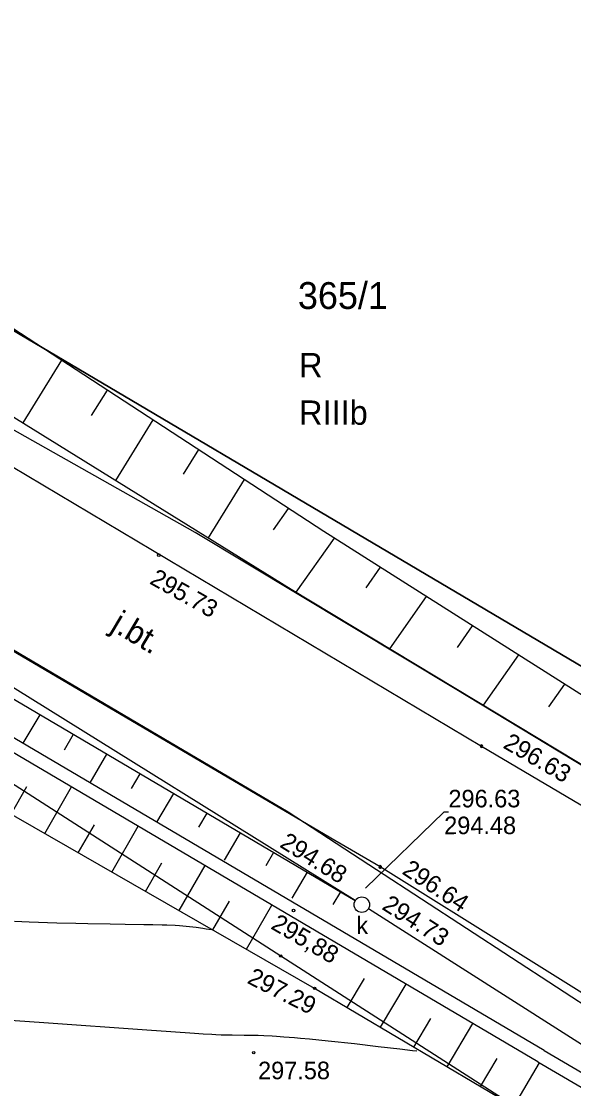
# Model space of a CAD drawing. Extents: x 7477803 to 7478145, y 5500698 to 5500984.
# Drawn here: x 7477973.66 to 7477995.02, y 5500861.83 to 5500903.15 of the extents above; entities that cross this region are included whole.
import ezdxf

# ---------------------------------------------------------------- set-up
doc = ezdxf.new("R2010")
doc.units = 0
for name, color, linetype in [('203-Punkt załamania granicy działki nie stabilizowany', 7, 'Continuous'), ('eNN', 7, 'Continuous'), ('gr_dzialki', 7, 'Continuous'), ('gr_klasy', 7, 'Continuous'), ('jezdnia', 7, 'Continuous'), ('k', 7, 'Continuous'), ('k_elem_naziemne', 7, 'Continuous'), ('k_rzedne', 7, 'Continuous'), ('nr_dzialki', 7, 'Continuous'), ('opis_klasy', 7, 'Continuous'), ('opis_uzytek', 7, 'Continuous'), ('opisy_drog', 7, 'Continuous'), ('pkt_wys', 7, 'Continuous'), ('rowy', 7, 'Continuous'), ('skarp_wypel', 7, 'Continuous'), ('skarpa_gora', 7, 'Continuous'), ('w', 7, 'Continuous'), ('warst_ciagla', 7, 'Continuous'), ('warst_przeryw', 7, 'Continuous')]:
    doc.layers.add(name, color=color, linetype=linetype)

# ---------------------------------------------------------------- blocks, each defined once
blk = doc.blocks.new('203')
blk.add_circle((0, 0), 0.045)
blk = doc.blocks.new('506_5_1')
at = {"layer": 'k_elem_naziemne'}
blk.add_circle((0, 0), 0.3, dxfattribs=at)
blk = doc.blocks.new('801_3')
at = {"layer": 'pkt_wys'}
blk.add_circle((0, 0), 0.045, dxfattribs=at)
blk.add_circle((0, 0), 0.045, dxfattribs=at)
blk = doc.blocks.new('801_5')
at = {"layer": 'pkt_wys'}
blk.add_circle((0, 0), 0.05, dxfattribs=at)
blk.add_circle((0, 0), 0.05, dxfattribs=at)
blk = doc.blocks.new('801_5_4')
at = {"layer": 'pkt_wys'}
blk.add_circle((0, 0), 0.05, dxfattribs=at)
blk.add_circle((0, 0), 0.05, dxfattribs=at)

msp = doc.modelspace()

# ---------------------------------------------------------------- linework, layer by layer
at = {"layer": 'eNN'}
msp.add_lwpolyline([(7478044.292, 5500829.332), (7478043.979, 5500830.08), (7478036.967, 5500842.126), (7478033.374, 5500847.92), (7478030.266, 5500851.792), (7478027.179, 5500855.154), (7478025.031, 5500856.9), (7478008.369, 5500866.572), (7477997.07, 5500873.297), (7477990.438, 5500877.31), (7477980.374, 5500883.358), (7477966.627, 5500891.122), (7477956.111, 5500897.36), (7477948.099, 5500902.324), (7477944.454, 5500904.573)], dxfattribs=at)
at = {"layer": 'gr_dzialki'}
for points in [[(7477995.4, 5500878.14), (7477967.16, 5500894.83)], [(7477983.69, 5500866.96), (7477970.37, 5500875.52)], [(7478015.58, 5500846.47), (7477983.69, 5500866.96)]]:
    msp.add_lwpolyline(points, dxfattribs=at)
at = {"layer": 'gr_klasy'}
for points in [[(7477967.16, 5500894.83), (7477995.4, 5500878.14)], [(7477983.69, 5500866.96), (7477970.37, 5500875.52)], [(7478015.58, 5500846.47), (7477983.69, 5500866.96)]]:
    msp.add_lwpolyline(points, dxfattribs=at)
at = {"layer": 'jezdnia'}
for points in [[(7477987.535, 5500870.412), (7477985.624, 5500871.53), (7477967.072, 5500882.45), (7477949.37, 5500893.011), (7477933.46, 5500902.673), (7477915.126, 5500915.133), (7477901.636, 5500924.498), (7477893.479, 5500930.51)], [(7477953.13, 5500897.937), (7477970.226, 5500887.733), (7477991.46, 5500875.087)], [(7477991.46, 5500875.087), (7478007.83, 5500865.404), (7478012.783, 5500862.5)], [(7478010.61, 5500855.711), (7478003.516, 5500860.43), (7477987.535, 5500870.412)]]:
    msp.add_lwpolyline(points, dxfattribs=at)
at = {"layer": 'k'}
msp.add_line((7477986.572, 5500869.11), (7477945.873, 5500894.448), dxfattribs=at)
msp.add_lwpolyline([(7477999.978, 5500860.567), (7477987.079, 5500868.79)], dxfattribs=at)
at = {"layer": 'k_rzedne'}
msp.add_lwpolyline([(7477990.178, 5500872.537), (7477989.998, 5500872.537), (7477986.973, 5500869.585)], dxfattribs=at)
at = {"layer": 'pkt_wys'}
for points in [[(7477991.428, 5500875.048), (7477991.46, 5500875.087), (7477991.434, 5500875.13)], [(7477991.434, 5500875.13), (7477991.46, 5500875.087), (7477991.428, 5500875.048)], [(7477991.428, 5500875.048), (7477991.46, 5500875.087), (7477991.434, 5500875.13)], [(7477991.434, 5500875.13), (7477991.46, 5500875.087), (7477991.428, 5500875.048)], [(7477987.495, 5500870.382), (7477987.535, 5500870.412), (7477987.567, 5500870.451)], [(7477987.567, 5500870.451), (7477987.535, 5500870.412), (7477987.495, 5500870.382)], [(7477987.495, 5500870.382), (7477987.535, 5500870.412), (7477987.567, 5500870.451)], [(7477987.567, 5500870.451), (7477987.535, 5500870.412), (7477987.495, 5500870.382)]]:
    msp.add_lwpolyline(points, dxfattribs=at)
for centre, start, end in [((7477991.46, 5500875.087), 120.6707, 229.9806), ((7477991.46, 5500875.087), 120.6707, 229.9806), ((7477991.46, 5500875.087), 229.9806, 120.6707), ((7477991.46, 5500875.087), 229.9806, 120.6707), ((7477987.535, 5500870.412), 49.9806, 217.4739), ((7477987.535, 5500870.412), 49.9806, 217.4739), ((7477987.535, 5500870.412), 217.4739, 49.9806), ((7477987.535, 5500870.412), 217.4739, 49.9806)]:
    msp.add_arc(centre, 0.05, start, end, dxfattribs=at)
at = {"layer": 'rowy'}
for points in [[(7477993.882, 5500863.302), (7477915.697, 5500909.43), (7477904.458, 5500915.769)], [(7477993.629, 5500862.871), (7477915.447, 5500908.997), (7477904.213, 5500915.334)], [(7477993.882, 5500863.302), (7478006.843, 5500855.712)], [(7477993.629, 5500862.871), (7478006.577, 5500855.288)]]:
    msp.add_lwpolyline(points, dxfattribs=at)
at = {"layer": 'skarp_wypel'}
for p, q in [((7477975.208, 5500890.03), (7477973.711, 5500887.602)), ((7477976.973, 5500888.876), (7477976.362, 5500887.883)), ((7477978.739, 5500887.722), (7477977.294, 5500885.378)), ((7477980.504, 5500886.568), (7477979.919, 5500885.618)), ((7477982.27, 5500885.414), (7477980.877, 5500883.155)), ((7477983.983, 5500884.294), (7477983.402, 5500883.467)), ((7477985.753, 5500883.145), (7477984.278, 5500881.047)), ((7477987.535, 5500882.014), (7477986.979, 5500881.224)), ((7477989.317, 5500880.883), (7477987.896, 5500878.862)), ((7477991.099, 5500879.752), (7477990.51, 5500878.913)), ((7477992.882, 5500878.621), (7477991.515, 5500876.677)), ((7477994.664, 5500877.49), (7477994.044, 5500876.609)), ((7477974.369, 5500876.302), (7477973.718, 5500875.198)), ((7477975.661, 5500875.54), (7477975.306, 5500874.938)), ((7477976.953, 5500874.778), (7477976.302, 5500873.674)), ((7477978.245, 5500874.016), (7477977.908, 5500873.443)), ((7477973.258, 5500872.455), (7477973.873, 5500873.525)), ((7477974.559, 5500871.708), (7477975.594, 5500873.511)), ((7477979.537, 5500873.254), (7477978.886, 5500872.149)), ((7477980.829, 5500872.492), (7477980.509, 5500871.948)), ((7477975.86, 5500870.961), (7477976.483, 5500872.046)), ((7477977.161, 5500870.214), (7477978.178, 5500871.987)), ((7477982.121, 5500871.73), (7477981.497, 5500870.672)), ((7477978.461, 5500869.467), (7477979.092, 5500870.566)), ((7477983.413, 5500870.968), (7477983.11, 5500870.453)), ((7477979.762, 5500868.72), (7477980.762, 5500870.462)), ((7477984.706, 5500870.206), (7477984.116, 5500869.206)), ((7477985.998, 5500869.444), (7477985.711, 5500868.958)), ((7477981.063, 5500867.974), (7477981.702, 5500869.086)), ((7477982.364, 5500867.227), (7477983.346, 5500868.937)), ((7477986.256, 5500864.969), (7477986.924, 5500866.096)), ((7477987.547, 5500864.204), (7477988.537, 5500865.875)), ((7477988.837, 5500863.439), (7477989.495, 5500864.549)), ((7477990.128, 5500862.675), (7477991.121, 5500864.351)), ((7477991.418, 5500861.91), (7477992.065, 5500863.002)), ((7477992.709, 5500861.145), (7477993.705, 5500862.826))]:
    msp.add_line(p, q, dxfattribs=at)
at = {"layer": 'skarpa_gora'}
for points in [[(7478007.879, 5500866.795), (7478009.357, 5500868.166), (7477985.351, 5500883.4), (7477939.898, 5500913.11), (7477944.561, 5500919.785), (7477954.951, 5500928.707), (7477971.014, 5500935.434), (7477981.218, 5500940.405), (7477991.643, 5500944.907), (7477994.866, 5500942.92), (7478002.778, 5500931.769), (7478021.266, 5500905.519), (7478029.289, 5500903.308), (7478032.779, 5500894.332), (7478047.773, 5500881.148)], [(7478007.879, 5500866.795), (7477984.093, 5500881.159), (7477934.83, 5500911.735), (7477933.524, 5500917.153), (7477941.313, 5500926.602), (7477947.253, 5500931.749), (7477948.257, 5500932.619)], [(7478019.361, 5500843.679), (7478014.009, 5500848.521), (7477985, 5500865.71), (7477963.897, 5500877.826), (7477945.275, 5500888.626), (7477927.783, 5500899.247), (7477912.023, 5500908.9), (7477901.238, 5500913.008)], [(7477986.568, 5500869.104), (7477965.993, 5500881.239), (7477948.007, 5500891.789)]]:
    msp.add_lwpolyline(points, dxfattribs=at)
at = {"layer": 'w'}
for points in [[(7477987.395, 5500870.305), (7477983.982, 5500872.534), (7477949.726, 5500892.741)], [(7478023.125, 5500842.409), (7478018.943, 5500849.443), (7477996.094, 5500864.625), (7477987.395, 5500870.305)]]:
    msp.add_lwpolyline(points, dxfattribs=at)
at = {"layer": 'warst_ciagla'}
msp.add_lwpolyline([(7477980.996, 5500867.973), (7477980.805, 5500868.008), (7477980.677, 5500868.03), (7477980.419, 5500868.066), (7477980.29, 5500868.082), (7477980.032, 5500868.108), (7477979.776, 5500868.129), (7477979.607, 5500868.14), (7477979.278, 5500868.156), (7477979.098, 5500868.163), (7477978.746, 5500868.172), (7477978.398, 5500868.177), (7477977.678, 5500868.183), (7477977.089, 5500868.191), (7477976.226, 5500868.208), (7477975.761, 5500868.22), (7477975.023, 5500868.241), (7477973.96, 5500868.276), (7477973.396, 5500868.297)], dxfattribs=at)
at = {"layer": 'warst_przeryw'}
msp.add_lwpolyline([(7477970.994, 5500864.637), (7477974.521, 5500864.386), (7477978.504, 5500864.104), (7477979.432, 5500864.04), (7477980.359, 5500863.977), (7477980.69, 5500863.955), (7477981.03, 5500863.934), (7477981.18, 5500863.926), (7477981.384, 5500863.918), (7477981.813, 5500863.907), (7477982.281, 5500863.903), (7477982.625, 5500863.901), (7477982.818, 5500863.897), (7477983.033, 5500863.889), (7477983.355, 5500863.872), (7477983.532, 5500863.861), (7477983.815, 5500863.84), (7477984.228, 5500863.806), (7477984.45, 5500863.787), (7477984.8, 5500863.754), (7477985.522, 5500863.682), (7477986.544, 5500863.573), (7477987.464, 5500863.467), (7477988.297, 5500863.366), (7477988.789, 5500863.31), (7477988.948, 5500863.295)], dxfattribs=at)

# ---------------------------------------------------------------- block references
at = {"layer": '203-Punkt załamania granicy działki nie stabilizowany'}
msp.add_blockref('203', (7477983.69, 5500866.96), dxfattribs=at)
at = {"layer": 'k_elem_naziemne', "rotation": 0.0626175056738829}
msp.add_blockref('506_5_1', (7477986.826, 5500868.952), dxfattribs=at)
at = {"layer": 'pkt_wys', "rotation": 0.0626175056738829}
for name, p in [('801_5', (7477978.972, 5500882.483)), ('801_5_4', (7477984.187, 5500868.729)), ('801_3', (7477985, 5500865.71)), ('801_3', (7477982.643, 5500863.217))]:
    msp.add_blockref(name, p, dxfattribs=at)

# ---------------------------------------------------------------- texts
at = {"layer": 'k_elem_naziemne'}
msp.add_text('k', height=0.68, rotation=0.0626, dxfattribs=at).set_placement((7477986.617, 5500867.812))
at = {"layer": 'k_rzedne'}
for s, rotation, p in [('296.63', 0.0626, (7477990.177, 5500872.717)), ('294.48', 0.0626, (7477990.013, 5500871.681)), ('294.68', 328.0948, (7477983.613, 5500871.209)), ('294.73', 327.4817, (7477987.567, 5500868.798))]:
    msp.add_text(s, height=0.68, rotation=rotation, dxfattribs=at).set_placement(p)
at = {"layer": 'nr_dzialki'}
msp.add_text('365/1', height=1.04, dxfattribs=at).set_placement((7477984.354, 5500892.013))
at = {"layer": 'opis_klasy'}
msp.add_text('RIIIb', height=0.94, dxfattribs=at).set_placement((7477984.4, 5500887.53))
at = {"layer": 'opis_uzytek'}
msp.add_text('R', height=0.94, dxfattribs=at).set_placement((7477984.4, 5500889.37))
at = {"layer": 'opisy_drog'}
msp.add_text('j.bt.', height=0.9, rotation=329.3232, dxfattribs=at).set_placement((7477977.064, 5500879.605))
at = {"layer": 'pkt_wys'}
for s, rotation, p in [('295.73', 330.5238, (7477978.58, 5500881.399)), ('296.63', 329.8429, (7477992.252, 5500875.044)), ('296.64', 326.3125, (7477988.347, 5500870.172)), ('295,88', 329.6771, (7477983.268, 5500868.045)), ('297.29', 333.1349, (7477982.352, 5500865.934)), ('297.58', 0.0626, (7477982.813, 5500862.192))]:
    msp.add_text(s, height=0.68, rotation=rotation, dxfattribs=at).set_placement(p)

doc.saveas('drawing.dxf')
